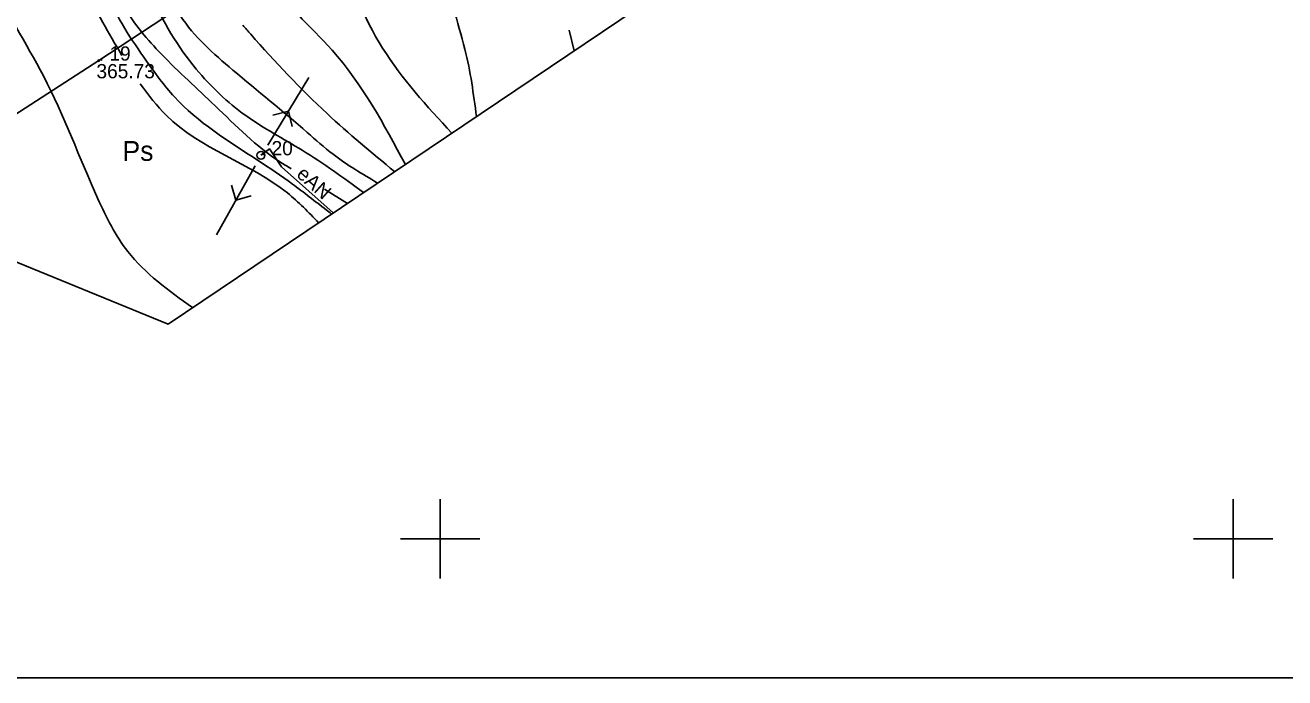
# Model space of a CAD drawing. Extents: x 4632591 to 4651936, y 5351032 to 5369988.
# Drawn here: x 4638423.8 to 4638503.3, y 5357941.2 to 5357982.4 of the extents above; entities that cross this region are included whole.
import ezdxf

# ---------------------------------------------------------------- set-up
doc = ezdxf.new("R2010")
doc.units = 0
for name, color, linetype in [('EBUPP_312', 7, 'Continuous'), ('EDZPD_219', 7, 'Continuous'), ('EKLPK_209', 7, 'Continuous'), ('UEEPA_510', 7, 'Continuous'), ('UEEPO_585', 7, 'Continuous'), ('UEETA_516', 7, 'Continuous'), ('Warstwa 40', 7, 'Continuous'), ('Warstwa 60', 7, 'Continuous'), ('Warstwa 62', 7, 'Continuous'), ('WUKPS_403', 7, 'Continuous'), ('WWRPH_811', 7, 'Continuous'), ('WWRPH_812', 7, 'Continuous'), ('WWRPH_814', 7, 'Continuous')]:
    doc.layers.add(name, color=color, linetype=linetype)

msp = doc.modelspace()

# ---------------------------------------------------------------- linework, layer by layer
at = {"layer": 'EBUPP_312'}
msp.add_lwpolyline([(4638382.7270229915, 5358114.561015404), (4638591.48324552, 5358114.561015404), (4638591.48324552, 5357941.242353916), (4638382.7270229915, 5357941.242353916), (4638382.7270229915, 5358114.561015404)], dxfattribs=at)
at = {"layer": 'EDZPD_219'}
for p, q in [((4638428.49, 5357980.16), (4638470.0200000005, 5358007.53)), ((4638418.666355, 5357973.84137348), (4638428.49, 5357980.16))]:
    msp.add_line(p, q, dxfattribs=at)
at = {"layer": 'UEEPA_510'}
msp.add_circle((4638438.71, 5357974.19), 0.25, dxfattribs=at)
at = {"layer": 'UEEPO_585'}
msp.add_lwpolyline([(4638438.71, 5357974.19), (4638439.238879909, 5357974.598724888), (4638440.014410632, 5357973.465256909), (4638443.259962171, 5357970.553533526)], dxfattribs=at)
at = {"layer": 'UEETA_516'}
for p, q in [((4638439.14017029, 5357974.831252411), (4638441.73328378, 5357979.106268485)), ((4638440.436727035, 5357976.9687604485), (4638439.465573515, 5357976.730939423)), ((4638440.436727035, 5357976.9687604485), (4638440.674548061, 5357975.9976069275)), ((4638438.343404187, 5357973.53570075), (4638435.8994321, 5357969.173705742)), ((4638437.121418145, 5357971.354703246), (4638436.850209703, 5357972.317066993)), ((4638437.121418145, 5357971.354703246), (4638438.083781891, 5357971.625911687))]:
    msp.add_line(p, q, dxfattribs=at)
at = {"layer": 'Warstwa 40'}
for p, q in [((4638549.152447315, 5358041.831700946), (4638432.85217456, 5357963.547861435)), ((4638432.85217456, 5357963.547861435), (4638413.843957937, 5357971.301212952))]:
    msp.add_line(p, q, dxfattribs=at)
at = {"layer": 'Warstwa 60'}
for p, q in [((4638450, 5357947.5), (4638450, 5357952.5)), ((4638500, 5357947.5), (4638500, 5357952.5)), ((4638447.5, 5357950), (4638452.5, 5357950)), ((4638497.5, 5357950), (4638502.5, 5357950))]:
    msp.add_line(p, q, dxfattribs=at)
at = {"layer": 'WUKPS_403'}
msp.add_circle((4638428.49, 5357980.16), 0.045, dxfattribs=at)
at = {"layer": 'WWRPH_811'}
msp.add_line((4638444.159871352, 5357971.159278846), (4638442.717691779, 5357972.046773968), dxfattribs=at)
for points in [[(4638435.92321611, 5358029.499414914), (4638436.439662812, 5358028.716656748), (4638439.315906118, 5358021.8386836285), (4638442.879946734, 5358015.085764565), (4638447.757054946, 5358006.957250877), (4638448.820014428, 5358001.142237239), (4638450.945933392, 5357995.702385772), (4638451.508676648, 5357991.137912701), (4638450.508244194, 5357986.073223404), (4638451.571203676, 5357980.88348005), (4638452.294395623, 5357976.634775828)], [(4638425.399731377, 5358026.263207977), (4638425.622486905, 5358025.9654675), (4638431.625081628, 5358012.146994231), (4638434.188689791, 5358004.643750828), (4638435.689338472, 5357999.454007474), (4638434.813960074, 5357995.702385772), (4638432.813095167, 5357990.387588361), (4638432.437932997, 5357986.1357504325), (4638433.625946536, 5357983.009399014), (4638436.939879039, 5357979.570412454), (4638441.629406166, 5357975.631209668), (4638443.255108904, 5357974.2556150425), (4638446.066759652, 5357972.442840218)], [(4638447.811671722, 5357973.617372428), (4638443.192581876, 5357980.820953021), (4638439.253379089, 5357985.510480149), (4638438.753162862, 5357992.263399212), (4638440.628973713, 5357996.577764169), (4638442.0045683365, 5357999.891696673), (4638441.379298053, 5358003.893426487), (4638433.813527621, 5358022.15131877), (4638433.134592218, 5358023.574891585)], [(4638440.607069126, 5357973.345618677), (4638439.9411764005, 5357973.755398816), (4638435.8143925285, 5357977.3194394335), (4638432.437932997, 5357980.570844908), (4638430.1244329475, 5357983.509615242), (4638428.373676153, 5357989.824845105), (4638428.0610410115, 5357994.576899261), (4638429.048540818, 5357997.0180439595)]]:
    msp.add_spline(points, degree=3, dxfattribs=at)
at = {"layer": 'WWRPH_812'}
msp.add_line((4638458.146016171, 5357982.08139993), (4638458.451275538, 5357980.779084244), dxfattribs=at)
for points in [[(4638416.659635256, 5358040.902492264), (4638416.24343265, 5358038.345819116), (4638416.431013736, 5358033.406183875), (4638418.369351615, 5358029.77961623), (4638423.996784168, 5358022.4014268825), (4638426.685446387, 5358017.96200787), (4638428.186095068, 5358012.084467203), (4638431.437500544, 5358002.205196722), (4638432.31287894, 5357998.45357502), (4638431.750135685, 5357994.201737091), (4638430.749703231, 5357990.450115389), (4638430.687176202, 5357987.76145317), (4638431.750135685, 5357984.32246661), (4638434.626378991, 5357979.632939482), (4638437.752730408, 5357976.69416915), (4638441.316771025, 5357974.505723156), (4638445.178855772, 5357971.8451758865)], [(4638434.3930733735, 5357964.585068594), (4638430.312014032, 5357968.127966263), (4638428.436203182, 5357971.441898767), (4638424.997216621, 5357979.195250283), (4638421.745811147, 5357985.447953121), (4638420.557797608, 5357991.20043973), (4638420.432743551, 5357998.140939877), (4638413.429716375, 5358015.64850782), (4638410.115783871, 5358020.025399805), (4638407.677229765, 5358024.4022917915), (4638406.614270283, 5358028.716656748), (4638405.8014189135, 5358032.343224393), (4638405.8014189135, 5358033.521597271)], [(4638420.629971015, 5358016.4947545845), (4638425.997649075, 5358001.454872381), (4638426.685446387, 5357995.139642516), (4638426.747973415, 5357992.200872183), (4638427.810932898, 5357987.636399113), (4638428.936419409, 5357984.510047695), (4638430.1244329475, 5357982.196547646), (4638431.500027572, 5357980.133155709), (4638433.250784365, 5357977.8821826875), (4638438.503054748, 5357973.880452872), (4638440.691500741, 5357972.379804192), (4638442.817419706, 5357970.754101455), (4638443.163431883, 5357970.488557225)], [(4638450.743102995, 5357975.590572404), (4638446.381460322, 5357980.9460070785), (4638443.81785216, 5357987.323763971), (4638443.692798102, 5357994.514372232), (4638444.880811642, 5358000.892129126), (4638440.691500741, 5358012.334575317), (4638440.676726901, 5358012.367430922)], [(4638447.136533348, 5357973.162924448), (4638442.879946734, 5357976.819223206), (4638438.06536555, 5357981.821385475), (4638437.564654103, 5357982.390620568)]]:
    msp.add_spline(points, degree=3, dxfattribs=at)
at = {"layer": 'WWRPH_814'}
for points in [[(4638420.189851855, 5358009.16550997), (4638421.24559492, 5358005.331548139), (4638424.497000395, 5357991.388020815), (4638428.748838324, 5357982.571709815), (4638429.933889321, 5357980.492467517)], [(4638431.102666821, 5357978.693764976), (4638432.750568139, 5357976.69416915), (4638440.378865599, 5357971.817060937), (4638442.34348716, 5357969.9366374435)]]:
    msp.add_spline(points, degree=3, dxfattribs=at)

# ---------------------------------------------------------------- texts
at = {"layer": 'EKLPK_209'}
msp.add_text('Ps', height=1.25, dxfattribs=at).set_placement((4638429.983747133, 5357973.841373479))
at = {"layer": 'UEEPO_585'}
msp.add_text('eAN', height=0.9, rotation=318.09182162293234, dxfattribs=at).set_placement((4638440.891572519, 5357972.905152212))
at = {"layer": 'Warstwa 62'}
for s, p in [('. 19', (4638428.49, 5357980.16)), ('. 20', (4638438.71, 5357974.19))]:
    msp.add_text(s, height=0.9, dxfattribs=at).set_placement(p)
at = {"layer": 'WUKPS_403'}
msp.add_text('365.73', height=0.9, dxfattribs=at).set_placement((4638428.342412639, 5357979.046748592))

doc.saveas('drawing.dxf')
